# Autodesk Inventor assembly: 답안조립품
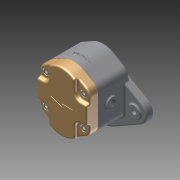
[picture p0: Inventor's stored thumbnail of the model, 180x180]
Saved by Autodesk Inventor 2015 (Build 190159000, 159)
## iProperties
Created: 2025-11
Part Number: 답안조립품
Document SubType Name: Assembly
Designer: user
Author: user
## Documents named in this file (11)
- C:\Users\user\Desktop\751103V1015\답안조립품.iam
- C:\Users\user\Desktop\751103V1015\가져온 구성요소\3자 실링\3자 실링.ipt
- C:\Users\user\Desktop\751103V1015\가져온 구성요소\6각 구멍붙이 볼트 M6x16\6각 구멍붙이 볼트 M6x16.ipt
- C:\Users\user\Desktop\751103V1015\가져온 구성요소\DU 부시\DU 부시.ipt
- C:\Users\user\Desktop\751103V1015\가져온 구성요소\가이드 블록\가이드 블록.ipt
- C:\Users\user\Desktop\751103V1015\가져온 구성요소\구동기어\구동기어.ipt
- C:\Users\user\Desktop\751103V1015\가져온 구성요소\스퍼기어\스퍼기어.ipt
- C:\Users\user\Desktop\751103V1015\가져온 구성요소\실링\실링.ipt
- C:\Users\user\Desktop\751103V1015\가져온 구성요소\오일 실 16 30 7\오일 실 16 30 7.ipt
- C:\Users\user\Desktop\751103V1015\가져온 구성요소\커버\커버.ipt
- C:\Users\user\Desktop\751103V1015\본체.ipt
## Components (11 placed, 5 different names)
1. 3자 실링:1
2. DU 부시:1
3. 가이드 블록:1
4. 구동기어:1
5. DU 부시:2
6. DU 부시:3
7. DU 부시:4
8. 6각 구멍붙이 볼트 M6x16:1
9. 6각 구멍붙이 볼트 M6x16:2
10. 6각 구멍붙이 볼트 M6x16:3
11. 6각 구멍붙이 볼트 M6x16:4
